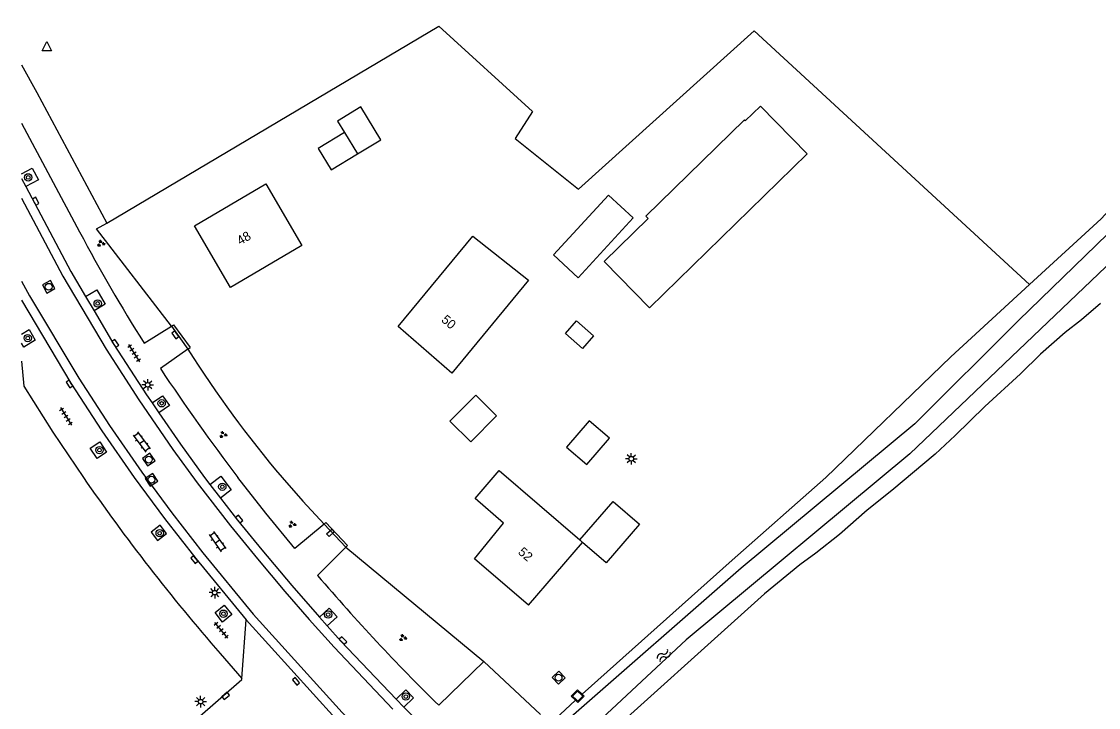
# Model space of a CAD drawing. Extents: x 135990 to 139000, y 393500 to 396000.
# Drawn here: x 136000 to 136117.3, y 395475 to 395549.6 of the extents above; entities that cross this region are included whole.
import ezdxf

# ---------------------------------------------------------------- set-up
doc = ezdxf.new("R2010")
doc.units = 0
for name, color, linetype in [('gg-afsc-erfafscheiding', 7, 'Continuous'), ('gg-afsc-hekwerk', 7, 'Continuous'), ('gg-anno-huisnummerreeks BGT', 7, 'Continuous'), ('gg-bbg-gedigitaliseerde bebouwing', 7, 'Continuous'), ('gg-bbg-gedigitaliseerde bijgebouw', 7, 'Continuous'), ('gg-bbg-hoofdgebouw', 7, 'Continuous'), ('gg-bbg-luifel en loopbrug', 7, 'Continuous'), ('gg-knt-onverhard', 7, 'Continuous'), ('gg-knt-verharding', 7, 'Continuous'), ('gg-kntw-bovenkant insteek waterloop', 7, 'Continuous'), ('gg-kwrk-uitstroombak niveau min 01', 7, 'Continuous'), ('gt-grn-groengrens', 7, 'Continuous'), ('gt-grn-vlakafsluiter', 7, 'Continuous'), ('gt-symb-boom', 7, 'Continuous'), ('gt-symb-groenvak', 7, 'Continuous'), ('gt-symb-klinker verharding', 7, 'Continuous'), ('gt-symb-kolk', 7, 'Continuous'), ('gt-symb-kolk center center', 7, 'Continuous'), ('gt-symb-lichtmast', 7, 'Continuous'), ('gt-symb-rioolschacht', 7, 'Continuous'), ('gt-symb-tegel verharding', 7, 'Continuous'), ('gt-symb-waterafsluiter', 7, 'Continuous'), ('gt-symb-watersymbool', 7, 'Continuous'), ('gx-grn-maaiveld', 7, 'Continuous')]:
    doc.layers.add(name, color=color, linetype=linetype)

# ---------------------------------------------------------------- blocks, each defined once
blk = doc.blocks.new('gt0-BOOM')
at = {"layer": 'gt-symb-boom'}
for radius in [0.4, 0.2]:
    blk.add_circle((0, 0), radius, dxfattribs=at)
blk = doc.blocks.new('gt0-GRVAK')
at = {"layer": 'gt-symb-groenvak'}
for p, q in [((-0.11, 0.19), (-0.23, 0.24)), ((-0.18, 0.15), (0.09, 0.15)), ((-0.09, 0.21), (-0.16, 0.32)), ((-0.05, 0.21), (-0.05, 0.39)), ((0, 0.21), (0.06, 0.32)), ((0.01, 0.19), (0.13, 0.24)), ((0.26, -0.05), (0.2, 0.06)), ((0.3, -0.05), (0.3, 0.13)), ((0.35, -0.05), (0.41, 0.06)), ((-0.25, -0.23), (-0.36, -0.18)), ((-0.32, -0.26), (-0.05, -0.26)), ((-0.23, -0.21), (-0.29, -0.09)), ((-0.18, -0.2), (-0.18, -0.02)), ((-0.14, -0.21), (-0.07, -0.09)), ((-0.12, -0.23), (0, -0.18)), ((0.24, -0.07), (0.12, -0.02)), ((0.17, -0.11), (0.44, -0.11)), ((0.37, -0.07), (0.49, -0.02))]:
    blk.add_line(p, q, dxfattribs=at)
blk = doc.blocks.new('gt0-KOLK')
at = {"layer": 'gt-symb-kolk'}
blk.add_lwpolyline([(0, 0), (0.38, 0), (0.38, 0.4), (-0.38, 0.4), (-0.38, 0), (0, 0)], dxfattribs=at)
blk = doc.blocks.new('gt0-WAFSL')
at = {"layer": 'gt-symb-waterafsluiter'}
for p, q in [((-0.5, -0.33), (0, 0.67)), ((0, 0.67), (0.5, -0.33)), ((0.5, -0.33), (-0.5, -0.33))]:
    blk.add_line(p, q, dxfattribs=at)
blk = doc.blocks.new('gt0-RS')
at = {"layer": 'gt-symb-rioolschacht'}
blk.add_lwpolyline([(-0.5, -0.5), (0.5, -0.5), (0.5, 0.5), (-0.5, 0.5)], close=True, dxfattribs=at)
blk.add_circle((0, 0), 0.375, dxfattribs=at)
blk = doc.blocks.new('gt0-TEG1')
at = {"layer": 'gt-symb-tegel verharding'}
for p, q in [((-1.12, 0), (1.12, 0)), ((-0.9, -0.25), (-0.9, 0.25)), ((-0.45, -0.25), (-0.45, 0.25)), ((0, -0.25), (0, 0.25)), ((0.45, -0.25), (0.45, 0.25)), ((0.9, -0.25), (0.9, 0.25))]:
    blk.add_line(p, q, dxfattribs=at)
blk = doc.blocks.new('gt0-LMAST')
at = {"layer": 'gt-symb-lichtmast'}
for p, q in [((-0.18, 0.17), (-0.45, 0.44)), ((-0.01, 0.25), (-0.01, 0.62)), ((0.17, 0.17), (0.44, 0.44)), ((-0.26, 0), (-0.63, 0)), ((-0.18, -0.18), (-0.45, -0.45)), ((-0.01, -0.25), (-0.01, -0.63)), ((0.44, -0.45), (0.17, -0.18)), ((0.24, 0), (0.62, 0))]:
    blk.add_line(p, q, dxfattribs=at)
blk.add_circle((-0.01, 0), 0.25, dxfattribs=at)
blk = doc.blocks.new('gt0-KL1')
at = {"layer": 'gt-symb-klinker verharding'}
for p, q in [((-1.15, 0.3), (1.15, 0.3)), ((-1, -0.3), (-1, 0.3)), ((-0.5, 0.3), (-0.5, 0.45)), ((0, -0.3), (0, 0.3)), ((0.5, 0.3), (0.5, 0.45)), ((1, -0.3), (1, 0.3)), ((-1.15, -0.3), (1.15, -0.3)), ((-0.5, -0.45), (-0.5, -0.3)), ((0.5, -0.45), (0.5, -0.3))]:
    blk.add_line(p, q, dxfattribs=at)
blk = doc.blocks.new('gt0-KOLKCC')
at = {"layer": 'gt-symb-kolk center center'}
blk.add_lwpolyline([(-0.38, 0.2), (0.38, 0.2), (0.38, -0.2), (-0.38, -0.2)], close=True, dxfattribs=at)
blk = doc.blocks.new('gt0-WA')
at = {"layer": 'gt-symb-watersymbool'}
for centre, start, end in [((-0.32, 0.02), 28.0725, 151.9275), ((0.43, 0.42), 208.0725, 331.9275), ((-0.32, -0.43), 28.0725, 151.9275), ((0.43, -0.03), 208.0725, 331.9275)]:
    blk.add_arc(centre, 0.425, start, end, dxfattribs=at)

msp = doc.modelspace()

# ---------------------------------------------------------------- linework, layer by layer
at = {"layer": 'gg-afsc-erfafscheiding'}
for p, q in [((136016.329, 395516.47), (136016.55, 395516.607)), ((136018.123, 395513.948), (136018.385, 395514.131)), ((136035.336, 395492.415), (136050.342, 395479.971))]:
    msp.add_line(p, q, dxfattribs=at)
for points in [[(136016.329, 395516.47), (136008.156, 395527.065), (136009.285, 395527.669)], [(136028.38, 395500), (136030.637, 395497.423), (136032.965, 395494.91)]]:
    msp.add_lwpolyline(points, dxfattribs=at)
msp.add_arc((136121.127, 395578.949), 121.799, 212.25417, 220.40545, dxfattribs=at)
at = {"layer": 'gg-afsc-hekwerk'}
for p, q in [((136001.659, 395541.917), (136009.285, 395527.669)), ((136001.659, 395541.917), (136009.285, 395527.669)), ((136016.55, 395516.607), (136018.385, 395514.131)), ((136050.342, 395479.971), (136056.516, 395474.187))]:
    msp.add_line(p, q, dxfattribs=at)
msp.add_lwpolyline([(136035.336, 395492.415), (136035.519, 395492.599), (136033.165, 395495.077), (136032.965, 395494.91)], dxfattribs=at)
at = {"layer": 'gg-bbg-gedigitaliseerde bebouwing'}
for p, q in [((136052.029, 395500.75), (136060.81, 395493.188)), ((136060.81, 395493.188), (136061.118, 395492.922))]:
    msp.add_line(p, q, dxfattribs=at)
msp.add_lwpolyline([(136041.031, 395516.421), (136049.151, 395526.274), (136055.211, 395521.462), (136046.871, 395511.331)], dxfattribs=at)
at = {"layer": 'gg-bbg-gedigitaliseerde bijgebouw'}
msp.add_line((136035.173, 395537.552), (136036.589, 395535.216), dxfattribs=at)
for points in [[(136085.57, 395535.22), (136080.49, 395540.43), (136078.84, 395538.82), (136078.75, 395538.91), (136068.02, 395528.44), (136068.27, 395528.19), (136063.48, 395523.52), (136068.42, 395518.47), (136085.57, 395535.22)], [(136035.173, 395537.552), (136032.315, 395535.82), (136033.731, 395533.484), (136036.589, 395535.216)], [(136066.64, 395528.25), (136063.95, 395530.74), (136057.94, 395524.22), (136060.63, 395521.73), (136066.64, 395528.25)], [(136059.246, 395515.668), (136060.451, 395517.037), (136062.319, 395515.393), (136061.114, 395514.024), (136059.246, 395515.668)], [(136046.662, 395506.116), (136049.489, 395508.946), (136051.753, 395506.684), (136048.926, 395503.854), (136046.662, 395506.116)], [(136059.382, 395503.277), (136061.589, 395501.395), (136064.043, 395504.273), (136061.835, 395506.155), (136059.382, 395503.277)]]:
    msp.add_lwpolyline(points, dxfattribs=at)
at = {"layer": 'gg-bbg-hoofdgebouw'}
for p, q in [((136046.871, 395511.331), (136041.031, 395516.421)), ((136055.231, 395486.09), (136061.118, 395492.922))]:
    msp.add_line(p, q, dxfattribs=at)
for points in [[(136022.751, 395520.691), (136018.831, 395527.381), (136026.601, 395531.951), (136030.531, 395525.261), (136022.751, 395520.691)], [(136055.231, 395486.09), (136049.341, 395491.14), (136052.51, 395495.014), (136049.428, 395497.699), (136052.029, 395500.75)]]:
    msp.add_lwpolyline(points, dxfattribs=at)
at = {"layer": 'gg-bbg-luifel en loopbrug'}
for points in [[(136036.589, 395535.216), (136039.135, 395536.759), (136036.972, 395540.327), (136034.427, 395538.784), (136035.173, 395537.552)], [(136060.81, 395493.188), (136064.433, 395497.374), (136067.306, 395494.889), (136063.683, 395490.702), (136061.118, 395492.922)]]:
    msp.add_lwpolyline(points, dxfattribs=at)
at = {"layer": 'gg-knt-onverhard'}
msp.add_line((136024.463, 395484.483), (136034.195, 395473.739), dxfattribs=at)
at = {"layer": 'gg-knt-verharding'}
for p, q in [((136000, 395538.552), (136006.326, 395526.733)), ((136000, 395532.538), (136000.461, 395531.674)), ((136006.976, 395519.706), (136007.894, 395518.148)), ((136013.343, 395514.622), (136016.329, 395516.47)), ((136016.329, 395516.47), (136018.123, 395513.948)), ((136018.123, 395513.948), (136015.121, 395511.851)), ((136014.227, 395508.102), (136014.963, 395507.025)), ((136020.525, 395499.243), (136021.689, 395497.739)), ((136035.336, 395492.415), (136032.965, 395494.91)), ((136032.256, 395489.322), (136035.336, 395492.415)), ((136024.01, 395478.121), (136024.463, 395484.483)), ((136032.441, 395484.795), (136033.289, 395483.853)), ((136021.621, 395480.827), (136024.01, 395478.121)), ((136045.44, 395475.187), (136050.342, 395479.971)), ((136041.654, 395474.984), (136040.797, 395475.848))]:
    msp.add_line(p, q, dxfattribs=at)
for points in [[(136000, 395533.031), (136001.14, 395533.648), (136001.835, 395532.404), (136000.461, 395531.674)], [(136000.461, 395531.674), (136005.385, 395522.404), (136006.976, 395519.706)], [(136000, 395530.41), (136004.512, 395521.915), (136009.211, 395513.944), (136012.787, 395508.435), (136016.492, 395503.021), (136019.132, 395499.41), (136022.758, 395494.724), (136025.689, 395491.119), (136028.688, 395487.575), (136031.346, 395484.516), (136034.062, 395481.5), (136040.433, 395474.778)], [(136000, 395521.359), (136000.875, 395519.78), (136006.237, 395510.8), (136009.584, 395505.64), (136013.096, 395500.569), (136016.362, 395496.137), (136019.758, 395491.783), (136025.236, 395485.118), (136034.936, 395474.41), (136039.308, 395469.973), (136043.053, 395466.396), (136045.436, 395464.288), (136045.843, 395464.012)], [(136006.976, 395519.706), (136008.204, 395520.43), (136009.114, 395518.867), (136007.894, 395518.148)], [(136000, 395519.295), (136005.388, 395510.271), (136008.753, 395505.083), (136012.274, 395500), (136015.565, 395495.533), (136018.977, 395491.158), (136024.463, 395484.483)], [(136007.894, 395518.148), (136010.062, 395514.47), (136013.619, 395508.99), (136014.227, 395508.102)], [(136000, 395515.604), (136000.824, 395516.099), (136001.495, 395514.927), (136000.255, 395514.182), (136000, 395514.627)], [(136000, 395512.67), (136000.247, 395509.922), (136003.423, 395504.918), (136006.732, 395500)], [(136014.227, 395508.102), (136015.369, 395508.884), (136016.122, 395507.818), (136014.963, 395507.025)], [(136014.963, 395507.025), (136017.308, 395503.599), (136019.939, 395500), (136020.525, 395499.243)], [(136007.485, 395503.164), (136008.512, 395503.864), (136009.266, 395502.74), (136008.238, 395502.039), (136007.485, 395503.164)], [(136020.525, 395499.243), (136021.695, 395500.149), (136022.842, 395498.631), (136021.689, 395497.739)], [(136032.965, 395494.91), (136029.775, 395492.247), (136026.628, 395496.088), (136023.568, 395500)], [(136021.689, 395497.739), (136023.541, 395495.346), (136026.171, 395492.112), (136029.447, 395488.226), (136032.441, 395484.795)], [(136014.113, 395494.02), (136014.812, 395493.123), (136015.783, 395493.882), (136015.084, 395494.78), (136014.113, 395494.02)], [(136021.083, 395485.29), (136022.072, 395486.097), (136022.895, 395485.062), (136021.905, 395484.255), (136021.083, 395485.29)], [(136032.441, 395484.795), (136033.527, 395485.773), (136034.367, 395484.824), (136033.289, 395483.853)], [(136033.289, 395483.853), (136034.797, 395482.179), (136040.797, 395475.848)], [(136000, 395457.264), (136019.124, 395473.738), (136023.993, 395477.994), (136024.01, 395478.121)], [(136040.797, 395475.848), (136041.854, 395476.864), (136042.697, 395475.988), (136041.654, 395474.984)]]:
    msp.add_lwpolyline(points, dxfattribs=at)
for centre, radius, start, end in [((136172.552, 395614.954), 188.186, 207.95633, 212.21887), ((136197.277, 395632.75), 218.626, 213.57265, 217.38737), ((136188.47, 395625.763), 221.009, 214.68329, 220.97973), ((136202.689, 395635.072), 224.255, 220.53628, 225.47629), ((135966.917, 395398.671), 106.814, 40.74061, 45.59764)]:
    msp.add_arc(centre, radius, start, end, dxfattribs=at)
at = {"layer": 'gg-kntw-bovenkant insteek waterloop'}
msp.add_line((136057.587, 395473.185), (136060.344, 395475.735), dxfattribs=at)
msp.add_lwpolyline([(136109.803, 395520.986), (136101.231, 395513.137), (136087.625, 395500), (136077.411, 395491), (136061.076, 395476.391)], dxfattribs=at)
at = {"layer": 'gg-kwrk-uitstroombak niveau min 01'}
for points in [[(136061.076, 395476.391), (136060.568, 395476.883), (136059.883, 395476.18), (136060.344, 395475.735)], [(136061.001, 395476.324), (136060.57, 395476.741), (136060.025, 395476.182), (136060.418, 395475.802)], [(136061.076, 395476.391), (136061.283, 395476.191), (136060.597, 395475.491), (136060.344, 395475.735)], [(136061.001, 395476.324), (136061.141, 395476.189), (136060.595, 395475.631), (136060.418, 395475.802)]]:
    msp.add_lwpolyline(points, dxfattribs=at)
at = {"layer": 'gt-grn-groengrens'}
msp.add_lwpolyline([(136009.285, 395527.669), (136045.454, 395549.132), (136055.664, 395539.84), (136053.763, 395536.88), (136060.683, 395531.383), (136079.805, 395548.614), (136109.803, 395520.986)], dxfattribs=at)
at = {"layer": 'gt-grn-vlakafsluiter'}
msp.add_line((136000, 395544.916), (136001.659, 395541.917), dxfattribs=at)
at = {"layer": 'gx-grn-maaiveld'}
for points in [[(136180.962, 395583.118), (136165.224, 395570.322), (136128.021, 395535.901), (136108.585, 395517.096), (136097.297, 395505.833), (136078.395, 395490.105), (136059.53, 395473.631), (136058.633, 395472.205)], [(136182.879, 395580.6), (136177.305, 395576.188), (136134.703, 395538.743), (136096.759, 395502.581), (136072.404, 395482.308), (136060.515, 395471.262), (136059.894, 395471.024)], [(136109.803, 395520.986), (136117.62, 395528.144), (136119.791, 395530.506), (136124.339, 395535.326), (136126.281, 395537.309), (136129.401, 395540.387), (136133.872, 395544.476), (136136.183, 395546.445), (136138.963, 395549.101), (136140.454, 395550.432)], [(136117.534, 395518.931), (136115.482, 395517.151), (136113.684, 395515.773), (136111.009, 395513.413), (136108.837, 395511.274), (136104.949, 395507.707), (136101.721, 395504.545), (136099.509, 395502.517), (136094.816, 395498.571), (136092.112, 395496.43), (136089.096, 395493.776), (136086.541, 395491.761), (136084.774, 395490.49), (136080.941, 395487.33), (136061.661, 395469.98), (136061.348, 395469.662)]]:
    msp.add_lwpolyline(points, dxfattribs=at)

# ---------------------------------------------------------------- block references
at = {"layer": 'gt-symb-boom'}
for p in [(136000.727, 395532.662), (136008.296, 395518.936), (136000.674, 395515.165), (136015.263, 395508.064), (136008.492, 395502.973), (136021.872, 395498.983), (136015.049, 395493.918), (136021.99, 395485.158), (136033.4, 395485.062), (136041.865, 395476.139)]:
    msp.add_blockref('gt0-BOOM', p, dxfattribs=at)
at = {"layer": 'gt-symb-groenvak'}
for p in [(136008.645, 395525.472), (136021.952, 395504.655), (136029.47, 395494.892), (136041.534, 395482.529)]:
    msp.add_blockref('gt0-GRVAK', p, dxfattribs=at)
at = {"layer": 'gt-symb-klinker verharding'}
for p, rotation in [((136013.083, 395503.854), -53.622932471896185), ((136021.331, 395493.012), -54.68878656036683)]:
    msp.add_blockref('gt0-KL1', p, dxfattribs=dict(at, rotation=rotation))
at = {"layer": 'gt-symb-kolk'}
for p, rotation in [((136001.37, 395529.973), -61.89717643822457), ((136010.062, 395514.47), -53.622932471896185), ((136016.923, 395515.635), 125.39110751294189), ((136005.388, 395510.271), 123.83302869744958), ((136023.541, 395495.346), -51.53705293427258), ((136018.977, 395491.158), 129.4022412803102), ((136035.161, 395482.376), 132.93289678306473), ((136030.053, 395477.913), 129.4386247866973), ((136022.106, 395476.353), -138.77095072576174)]:
    msp.add_blockref('gt0-KOLK', p, dxfattribs=dict(at, rotation=rotation))
at = {"layer": 'gt-symb-kolk center center', "rotation": 43.541582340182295}
msp.add_blockref('gt0-KOLKCC', (136033.648, 395493.959), dxfattribs=at)
at = {"layer": 'gt-symb-lichtmast'}
for p in [(136013.751, 395510.078), (136066.432, 395502.031), (136021.055, 395487.452), (136019.512, 395475.583)]:
    msp.add_blockref('gt0-LMAST', p, dxfattribs=at)
at = {"layer": 'gt-symb-rioolschacht'}
for p, rotation in [((136002.959, 395520.75), -61.512992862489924), ((136013.863, 395501.939), -55.51509196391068), ((136014.152, 395499.74), -56.3734708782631), ((136058.499, 395478.189), -46.458417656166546)]:
    msp.add_blockref('gt0-RS', p, dxfattribs=dict(at, rotation=rotation))
at = {"layer": 'gt-symb-tegel verharding'}
for p, rotation in [((136012.258, 395513.538), -57.788102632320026), ((136004.841, 395506.649), -57.78810263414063), ((136021.759, 395483.352), 129.724862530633)]:
    msp.add_blockref('gt0-TEG1', p, dxfattribs=dict(at, rotation=rotation))
at = {"layer": 'gt-symb-waterafsluiter'}
msp.add_blockref('gt0-WAFSL', (136002.748, 395546.78), dxfattribs=at)
at = {"layer": 'gt-symb-watersymbool', "rotation": 41.83814925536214}
msp.add_blockref('gt0-WA', (136069.922, 395480.576), dxfattribs=at)

# ---------------------------------------------------------------- texts
at = {"layer": 'gg-anno-huisnummerreeks BGT'}
for s, rotation, p in [('48', 30.4, (136023.816, 395525.249)), ('50', 318.9, (136045.653, 395517.037)), ('52', 319.4, (136054.013, 395491.744))]:
    msp.add_text(s, height=1, rotation=rotation, dxfattribs=at).set_placement(p)

doc.saveas('drawing.dxf')
